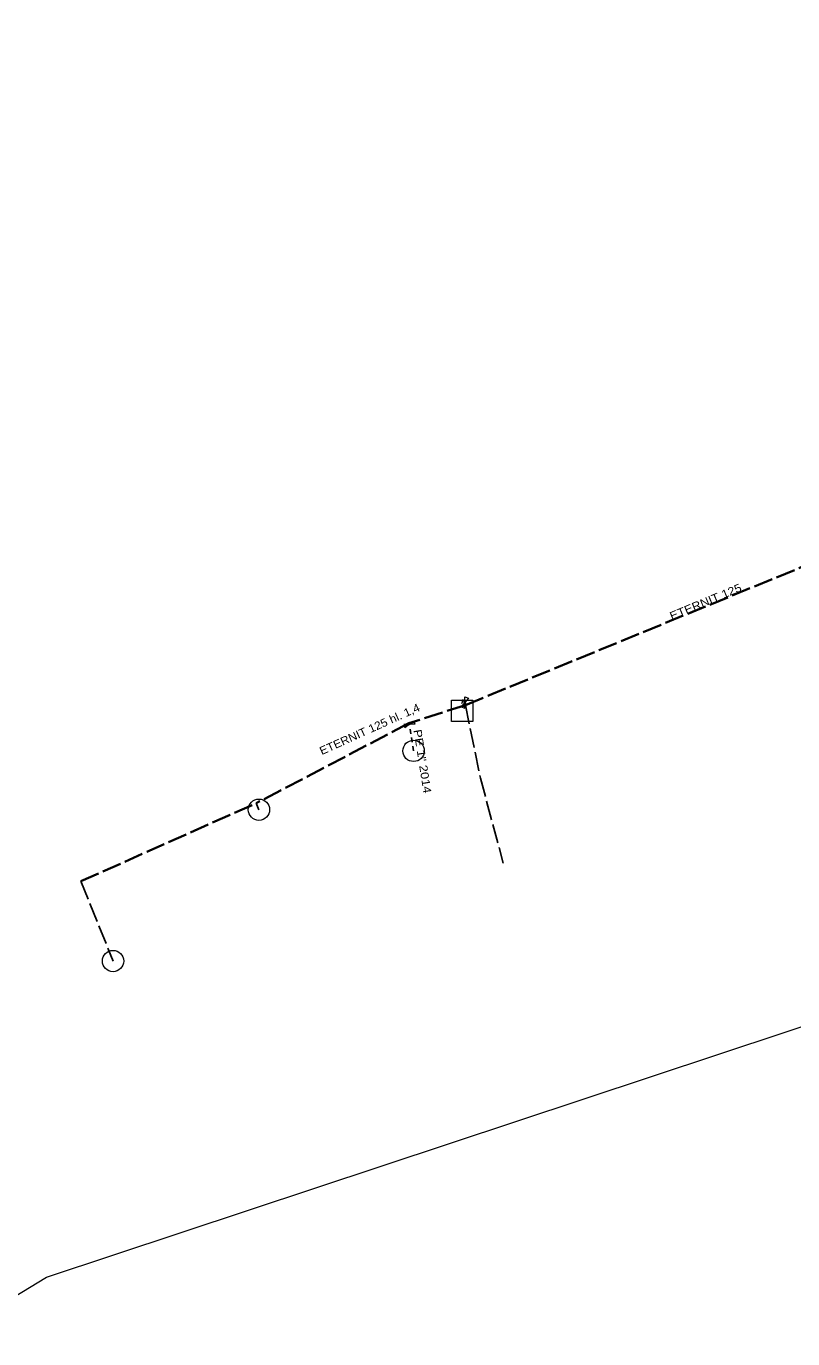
# Model space of a CAD drawing. Extents: x -616592 to -615844, y -1088988 to -1088174.
# Drawn here: x -616145.9 to -616074.1, y -1088431.2 to -1088308.2 of the extents above; entities that cross this region are included whole.
import ezdxf
from ezdxf.enums import TextEntityAlignment as Align

# ---------------------------------------------------------------- set-up
doc = ezdxf.new("R2010")
doc.units = 0
doc.header["$LTSCALE"] = 0.3
doc.linetypes.add('LONG_DASHED', pattern=[7.5, 6, -1.5])
doc.linetypes.add('SHORT_DASHED', pattern=[2.7, 1.5, -1.2])
for name, color, linetype, lineweight in [('1', 7, 'Continuous', 13), ('10', 7, 'Continuous', 13), ('35', 7, 'LONG_DASHED', 35), ('50', 7, 'LONG_DASHED', 25), ('51', 7, 'SHORT_DASHED', 25)]:
    doc.layers.add(name, color=color, linetype=linetype, lineweight=lineweight)
doc.layers.add('16', color=7, linetype='Continuous')
doc.layers.add('19', color=7, linetype='Continuous')

msp = doc.modelspace()

# ---------------------------------------------------------------- linework, layer by layer
at = {"layer": '1'}
msp.add_lwpolyline([(-616317.402, -1088743.479), (-616316.925, -1088623.142), (-616336.026, -1088584.94), (-616318.357, -1088562.497), (-616286.363, -1088552.469), (-616214.734, -1088468.424), (-616144.06, -1088425.447), (-616043.302, -1088392.02), (-615921.533, -1088342.835), (-615901, -1088273.116), (-615900.045, -1088185.251), (-615900.045, -1088185.251), (-615851.337, -1088190.027), (-615863.753, -1088293.172), (-615879.033, -1088367.189), (-615932.994, -1088397.75), (-616036.139, -1088431.177), (-616143.105, -1088462.216), (-616202.318, -1088518.087), (-616257.711, -1088587.328), (-616274.902, -1088683.788)], dxfattribs=at)
at = {"layer": '10'}
msp.add_line((-616105.093, -1088371.5), (-616105.183, -1088371.733), dxfattribs=at)
for points in [[(-616104.1, -1088371.38), (-616104.1, -1088373.38), (-616106.1, -1088373.38), (-616106.1, -1088371.38)], [(-616110.06, -1088373.633), (-616109.634, -1088373.331), (-616109.538, -1088373.616), (-616110.06, -1088373.633), (-616110.582, -1088373.65), (-616110.486, -1088373.935)]]:
    msp.add_lwpolyline(points, close=True, dxfattribs=at)
msp.add_lwpolyline([(-616104.86, -1088371.59), (-616104.854, -1088371.056), (-616104.505, -1088371.191), (-616104.86, -1088371.59), (-616105.215, -1088371.989), (-616104.866, -1088372.124), (-616104.86, -1088371.59), (-616105.093, -1088371.5), (-616105.003, -1088371.267)], dxfattribs=at)
for centre in [(-616109.663, -1088376.125), (-616124.15, -1088381.636), (-616137.816, -1088395.817)]:
    msp.add_circle(centre, 1, dxfattribs=at)
at = {"layer": '35'}
for p, q in [((-616104.798, -1088371.828), (-616053.69, -1088350.85)), ((-616104.798, -1088371.828), (-616104.86, -1088371.59)), ((-616140.826, -1088388.343), (-616124.391, -1088381.026))]:
    msp.add_line(p, q, dxfattribs=at)
msp.add_lwpolyline([(-616104.798, -1088371.828), (-616110.102, -1088373.542), (-616124.391, -1088381.026)], dxfattribs=at)
at = {"layer": '50'}
for p, q in [((-616104.798, -1088371.828), (-616103.4, -1088378.67)), ((-616103.4, -1088378.67), (-616101.259, -1088386.637)), ((-616124.391, -1088381.026), (-616124.15, -1088381.636)), ((-616140.826, -1088388.343), (-616137.816, -1088395.817))]:
    msp.add_line(p, q, dxfattribs=at)
at = {"layer": '51'}
msp.add_lwpolyline([(-616109.663, -1088376.125), (-616110.06, -1088373.633), (-616110.102, -1088373.542)], dxfattribs=at)

# ---------------------------------------------------------------- texts
at = {"layer": '16'}
for s, rotation, width, p in [('ETERNIT 125', 22.723, 1.15, (-616082.1629, -1088362.5022)), ('ETERNIT 125 hl. 1,4', 24.27, 1.1, (-616113.6221, -1088374.432))]:
    msp.add_text(s, height=0.75, rotation=rotation, dxfattribs=dict(at, width=width)).set_placement(p, align=Align.CENTER)
at = {"layer": '19', "width": 1.2}
msp.add_text('PE 1" 2014', height=0.75, rotation=279.052, dxfattribs=at).set_placement((-616109.1936, -1088377.166), align=Align.CENTER)

doc.saveas('drawing.dxf')
